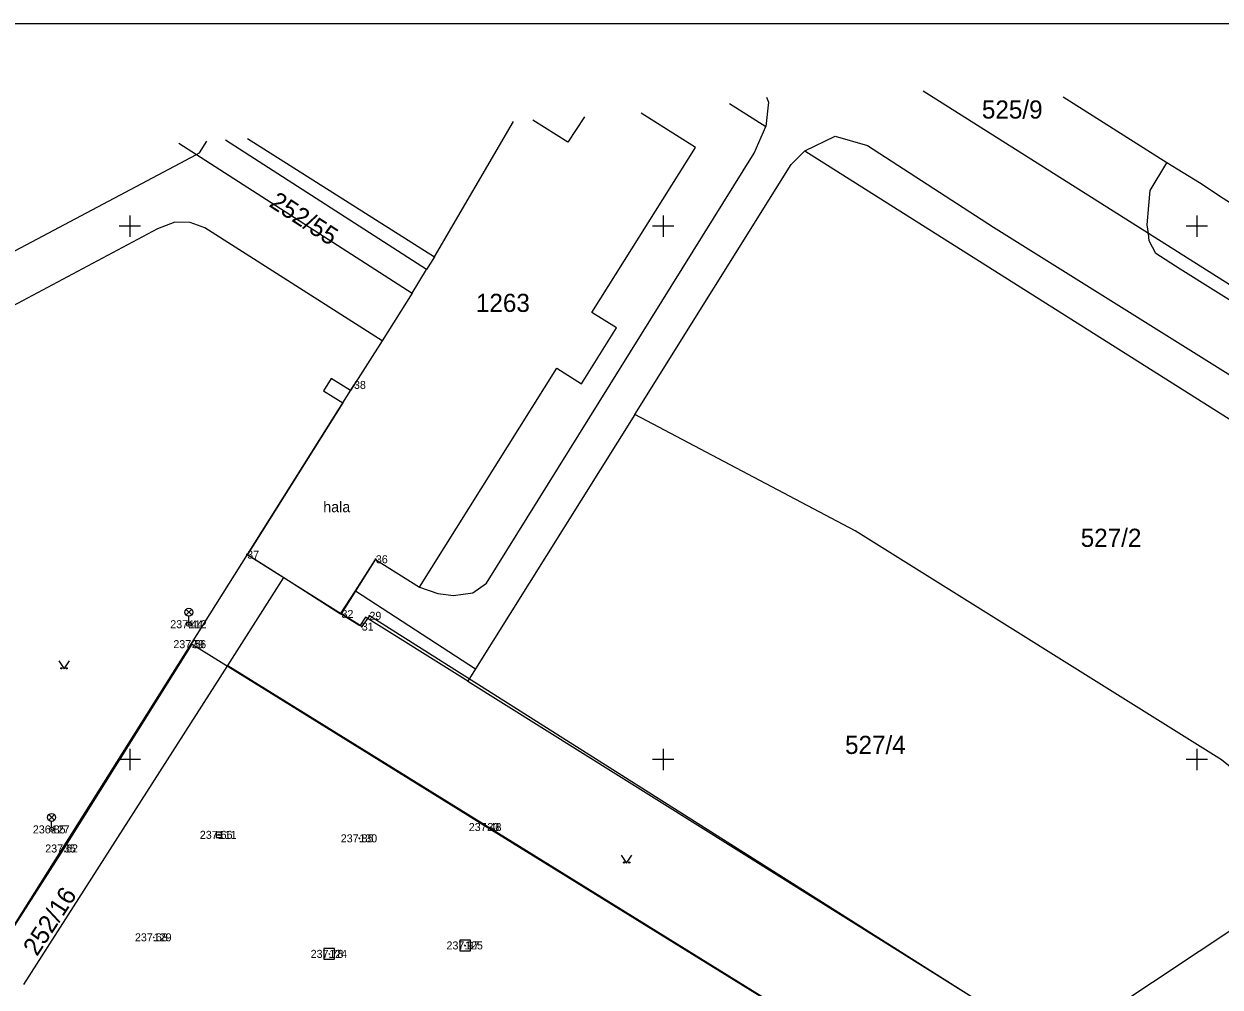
# Model space of a CAD drawing. Extents: x -645398 to -644998, y -1063322 to -1063031.
# Drawn here: x -645309.9 to -645197.8, y -1063121.3 to -1063031 of the extents above; entities that cross this region are included whole.
import ezdxf

# ---------------------------------------------------------------- set-up
doc = ezdxf.new("R2010")
doc.units = 0
for name, color, linetype in [('Bod', 7, 'Continuous'), ('Doplněk polohopisu', 7, 'Continuous'), ('Elektrický kabel', 7, 'Continuous'), ('Hranice KN pozemků', 7, 'Continuous'), ('Kanalizace', 7, 'Continuous'), ('Kultury', 7, 'Continuous'), ('Popisy budov', 7, 'Continuous'), ('Rozhraní ploch', 7, 'Continuous'), ('Rámeček', 7, 'Continuous'), ('Souřadnicové křížky', 7, 'Continuous'), ('Stavby', 7, 'Continuous'), ('Sítě podzemní nerozlišené', 7, 'Continuous'), ('Vnitřní kresba parcel', 7, 'Continuous'), ('Výška', 7, 'Continuous'), ('Čísla parcel', 7, 'Continuous'), ('Čísla stavebních parcel', 7, 'Continuous'), ('Číslo bodu', 7, 'Continuous')]:
    doc.layers.add(name, color=color, linetype=linetype)

msp = doc.modelspace()

# ---------------------------------------------------------------- linework, layer by layer
at = {"layer": 'Bod'}
for p, q in [((-645278.99, -1063064.87), (-645279.04, -1063064.82)), ((-645278.99, -1063064.87), (-645279.04, -1063064.92)), ((-645278.99, -1063064.87), (-645278.94, -1063064.82)), ((-645278.99, -1063064.87), (-645278.94, -1063064.92)), ((-645289, -1063080.79), (-645289.05, -1063080.74)), ((-645289, -1063080.79), (-645289.05, -1063080.84)), ((-645289, -1063080.79), (-645288.95, -1063080.74)), ((-645289, -1063080.79), (-645288.95, -1063080.84)), ((-645276.94, -1063081.23), (-645276.99, -1063081.18)), ((-645276.94, -1063081.23), (-645276.99, -1063081.28)), ((-645276.94, -1063081.23), (-645276.89, -1063081.18)), ((-645276.94, -1063081.23), (-645276.89, -1063081.28)), ((-645294.47, -1063087.31), (-645294.52, -1063087.26)), ((-645294.47, -1063087.31), (-645294.52, -1063087.36)), ((-645294.47, -1063087.31), (-645294.42, -1063087.26)), ((-645294.47, -1063087.31), (-645294.42, -1063087.36)), ((-645280.16, -1063086.35), (-645280.21, -1063086.3)), ((-645280.16, -1063086.35), (-645280.21, -1063086.4)), ((-645280.16, -1063086.35), (-645280.11, -1063086.3)), ((-645280.16, -1063086.35), (-645280.11, -1063086.4)), ((-645277.54, -1063086.52), (-645277.59, -1063086.47)), ((-645277.54, -1063086.52), (-645277.59, -1063086.57)), ((-645277.54, -1063086.52), (-645277.49, -1063086.47)), ((-645277.54, -1063086.52), (-645277.49, -1063086.57)), ((-645278.26, -1063087.53), (-645278.31, -1063087.48)), ((-645278.26, -1063087.53), (-645278.31, -1063087.58)), ((-645278.26, -1063087.53), (-645278.21, -1063087.48)), ((-645278.26, -1063087.53), (-645278.21, -1063087.58)), ((-645294.16, -1063089.19), (-645294.21, -1063089.14)), ((-645294.16, -1063089.19), (-645294.21, -1063089.24)), ((-645294.16, -1063089.19), (-645294.11, -1063089.14)), ((-645294.16, -1063089.19), (-645294.11, -1063089.24)), ((-645266.49, -1063106.33), (-645266.54, -1063106.28)), ((-645266.49, -1063106.33), (-645266.54, -1063106.38)), ((-645266.49, -1063106.33), (-645266.44, -1063106.28)), ((-645266.49, -1063106.33), (-645266.44, -1063106.38)), ((-645307.33, -1063106.55), (-645307.38, -1063106.5)), ((-645307.33, -1063106.55), (-645307.38, -1063106.6)), ((-645307.33, -1063106.55), (-645307.28, -1063106.5)), ((-645307.33, -1063106.55), (-645307.28, -1063106.6)), ((-645291.66, -1063107.06), (-645291.71, -1063107.01)), ((-645291.66, -1063107.06), (-645291.71, -1063107.11)), ((-645291.66, -1063107.06), (-645291.61, -1063107.01)), ((-645291.66, -1063107.06), (-645291.61, -1063107.11)), ((-645278.49, -1063107.4), (-645278.54, -1063107.35)), ((-645278.49, -1063107.4), (-645278.54, -1063107.45)), ((-645278.49, -1063107.4), (-645278.44, -1063107.35)), ((-645278.49, -1063107.4), (-645278.44, -1063107.45)), ((-645306.17, -1063108.34), (-645306.22, -1063108.29)), ((-645306.17, -1063108.34), (-645306.22, -1063108.39)), ((-645306.17, -1063108.34), (-645306.12, -1063108.29)), ((-645306.17, -1063108.34), (-645306.12, -1063108.39)), ((-645297.76, -1063116.68), (-645297.81, -1063116.63)), ((-645297.76, -1063116.68), (-645297.81, -1063116.73)), ((-645297.76, -1063116.68), (-645297.71, -1063116.63)), ((-645297.76, -1063116.68), (-645297.71, -1063116.73)), ((-645268.58, -1063117.44), (-645268.63, -1063117.39)), ((-645268.58, -1063117.44), (-645268.63, -1063117.49)), ((-645268.58, -1063117.44), (-645268.53, -1063117.39)), ((-645268.58, -1063117.44), (-645268.53, -1063117.49)), ((-645281.31, -1063118.23), (-645281.36, -1063118.18)), ((-645281.31, -1063118.23), (-645281.36, -1063118.28)), ((-645281.31, -1063118.23), (-645281.26, -1063118.18)), ((-645281.31, -1063118.23), (-645281.26, -1063118.28))]:
    msp.add_line(p, q, dxfattribs=at)
at = {"layer": 'Doplněk polohopisu'}
msp.add_lwpolyline([(-645213.53, -1063127.04), (-645277.54, -1063086.52), (-645278.26, -1063087.53), (-645280.16, -1063086.35)], dxfattribs=at)
at = {"layer": 'Elektrický kabel'}
for p, q in [((-645294.73, -1063086.45), (-645294.21, -1063085.92)), ((-645294.2, -1063086.45), (-645294.73, -1063085.92)), ((-645294.47, -1063087.11), (-645294.47, -1063086.56)), ((-645307.59, -1063105.69), (-645307.07, -1063105.16)), ((-645307.06, -1063105.69), (-645307.59, -1063105.16)), ((-645307.33, -1063106.35), (-645307.33, -1063105.8))]:
    msp.add_line(p, q, dxfattribs=at)
for centre, radius in [((-645294.47, -1063086.19), 0.375), ((-645294.47, -1063087.31), 0.2), ((-645307.33, -1063105.43), 0.375), ((-645307.33, -1063106.55), 0.2)]:
    msp.add_circle(centre, radius, dxfattribs=at)
at = {"layer": 'Hranice KN pozemků'}
for p, q in [((-645272.18, -1063054.06), (-645291.04, -1063041.91)), ((-645293.75, -1063043.27), (-645273.55, -1063056.26)), ((-645204.35, -1063046.64), (-645202.8, -1063044.04)), ((-645297.4, -1063050.24), (-645348.48, -1063077.49)), ((-645276.35, -1063060.75), (-645292.97, -1063050.16)), ((-645273.55, -1063056.26), (-645272.18, -1063054.06)), ((-645273.55, -1063056.26), (-645276.35, -1063060.75)), ((-645324.71, -1063137.53), (-645288.96, -1063080.79)), ((-645288.96, -1063080.79), (-645285.57, -1063082.93)), ((-645290.82, -1063091.17), (-645285.57, -1063082.93)), ((-645285.57, -1063082.93), (-645280.26, -1063086.33)), ((-645278.45, -1063087.48), (-645280.26, -1063086.33)), ((-645309.94, -1063121.11), (-645290.82, -1063091.17)), ((-645290.82, -1063091.17), (-645226.33, -1063131.14)), ((-645268.32, -1063092.65), (-645213.42, -1063127.02)), ((-645213.42, -1063127.02), (-645186.47, -1063109.12))]:
    msp.add_line(p, q, dxfattribs=at)
for points in [[(-645204.52, -1063050.69), (-645225.65, -1063037.34)], [(-645202.8, -1063044.04), (-645212.52, -1063037.89)], [(-645280.26, -1063086.33), (-645278.86, -1063084.17), (-645276.97, -1063081.25), (-645272.86, -1063083.83), (-645259.97, -1063063.31), (-645257.66, -1063064.76), (-645254.37, -1063059.51), (-645256.68, -1063058.07), (-645246.97, -1063042.62), (-645252.08, -1063039.39)], [(-645257.39, -1063039.73), (-645258.95, -1063042.11), (-645262.24, -1063040.05)], [(-645295.42, -1063042.19), (-645293.75, -1063043.27)], [(-645293.75, -1063043.27), (-645293.47, -1063043.12), (-645292.79, -1063042.02)], [(-645288.97, -1063041.78), (-645271.43, -1063052.86), (-645272.18, -1063054.06)], [(-645236.73, -1063042.91), (-645233.9, -1063041.56), (-645230.85, -1063042.43), (-645219.03, -1063050.07), (-645152.72, -1063091.57), (-645140.39, -1063099.29), (-645051.35, -1063155.61)], [(-645343.9, -1063052.83), (-645337.14, -1063056.96), (-645328.72, -1063059.37), (-645321.06, -1063057.75), (-645293.75, -1063043.27)], [(-645252.67, -1063067.66), (-645238, -1063044.21), (-645236.73, -1063042.91)], [(-645236.73, -1063042.91), (-645154.72, -1063094.74), (-645140.39, -1063103.8), (-645055.15, -1063157.46)], [(-645168.41, -1063048.3), (-645168.62, -1063048.16), (-645173.43, -1063055.26), (-645176.87, -1063060.58), (-645197.51, -1063047.38), (-645199.73, -1063045.93), (-645202.8, -1063044.04)], [(-645204.52, -1063050.69), (-645204.63, -1063049.86), (-645204.48, -1063048.05), (-645204.35, -1063046.64)], [(-645292.97, -1063050.16), (-645294.36, -1063049.64), (-645295.77, -1063049.62), (-645297.4, -1063050.24)], [(-645149.78, -1063063.57), (-645159.6, -1063079.08), (-645204.52, -1063050.69)], [(-645203.84, -1063052.54), (-645204.44, -1063051.35), (-645204.52, -1063050.69)], [(-645148.3, -1063087.54), (-645149.64, -1063086.69), (-645177.4, -1063069.18), (-645179.16, -1063068.05), (-645201.56, -1063054.02), (-645203.84, -1063052.54)], [(-645276.35, -1063060.75), (-645279.31, -1063065.41), (-645281.13, -1063064.28), (-645281.86, -1063065.42), (-645280.03, -1063066.56), (-645288.96, -1063080.79)], [(-645252.67, -1063067.66), (-645267.59, -1063091.49), (-645268.32, -1063092.65)], [(-645186.47, -1063109.12), (-645197.66, -1063100.03), (-645232, -1063078.56), (-645252.67, -1063067.66)], [(-645268.32, -1063092.65), (-645277.91, -1063086.64), (-645278.45, -1063087.48)]]:
    msp.add_lwpolyline(points, dxfattribs=at)
at = {"layer": 'Kanalizace'}
msp.add_line((-645291.91, -1063107.06), (-645291.41, -1063107.06), dxfattribs=at)
msp.add_lwpolyline([(-645291.91, -1063107.31), (-645291.41, -1063107.31), (-645291.41, -1063106.81), (-645291.91, -1063106.81)], close=True, dxfattribs=at)
at = {"layer": 'Kultury'}
for points in [[(-645306.67, -1063090.75), (-645306.17, -1063091.5), (-645305.67, -1063090.75)], [(-645253.93, -1063108.96), (-645253.43, -1063109.71), (-645252.93, -1063108.96)]]:
    msp.add_lwpolyline(points, dxfattribs=at)
for centre in [(-645306.42, -1063091.45), (-645305.92, -1063091.45), (-645253.68, -1063109.66), (-645253.18, -1063109.66)]:
    msp.add_circle(centre, 0.05, dxfattribs=at)
at = {"layer": 'Rozhraní ploch'}
msp.add_lwpolyline([(-645324.89, -1063137.57), (-645306.17, -1063108.34), (-645294.16, -1063089.19), (-645266.49, -1063106.33), (-645238.82, -1063123.47), (-645226.63, -1063131.07), (-645233.92, -1063142.75), (-645244.93, -1063160.38), (-645255.94, -1063178.02)], dxfattribs=at)
at = {"layer": 'Rámeček'}
msp.add_line((-644998.25, -1063031.02), (-645398.25, -1063031.02), dxfattribs=at)
at = {"layer": 'Souřadnicové křížky'}
for p, q in [((-645300, -1063049), (-645300, -1063051)), ((-645250, -1063049), (-645250, -1063051)), ((-645200, -1063049), (-645200, -1063051)), ((-645299, -1063050), (-645301, -1063050)), ((-645249, -1063050), (-645251, -1063050)), ((-645199, -1063050), (-645201, -1063050)), ((-645300, -1063099), (-645300, -1063101)), ((-645250, -1063099), (-645250, -1063101)), ((-645200, -1063099), (-645200, -1063101)), ((-645299, -1063100), (-645301, -1063100)), ((-645249, -1063100), (-645251, -1063100)), ((-645199, -1063100), (-645201, -1063100))]:
    msp.add_line(p, q, dxfattribs=at)
at = {"layer": 'Stavby'}
for p, q in [((-645278.99, -1063064.87), (-645289, -1063080.79)), ((-645289, -1063080.79), (-645280.16, -1063086.35)), ((-645280.16, -1063086.35), (-645276.94, -1063081.23))]:
    msp.add_line(p, q, dxfattribs=at)
at = {"layer": 'Sítě podzemní nerozlišené'}
for p, q in [((-645268.08, -1063116.94), (-645269.08, -1063116.94)), ((-645269.08, -1063116.94), (-645269.08, -1063117.94)), ((-645268.08, -1063117.94), (-645268.08, -1063116.94)), ((-645280.81, -1063117.73), (-645281.81, -1063117.73)), ((-645281.81, -1063117.73), (-645281.81, -1063118.73)), ((-645280.81, -1063118.73), (-645280.81, -1063117.73)), ((-645269.08, -1063117.94), (-645268.08, -1063117.94)), ((-645281.81, -1063118.73), (-645280.81, -1063118.73))]:
    msp.add_line(p, q, dxfattribs=at)
at = {"layer": 'Vnitřní kresba parcel'}
for p, q in [((-645240.33, -1063037.88), (-645240.13, -1063038.36)), ((-645243.8, -1063038.48), (-645240.37, -1063040.65)), ((-645240.13, -1063038.36), (-645240.37, -1063040.65)), ((-645271.43, -1063052.86), (-645264.04, -1063040.16)), ((-645241.47, -1063043.14), (-645240.37, -1063040.65)), ((-645266.56, -1063083.48), (-645241.47, -1063043.14)), ((-645272.86, -1063083.83), (-645271.12, -1063084.43)), ((-645267.84, -1063084.37), (-645266.56, -1063083.48)), ((-645278.86, -1063084.17), (-645267.59, -1063091.49)), ((-645271.12, -1063084.43), (-645269.65, -1063084.61)), ((-645269.65, -1063084.61), (-645267.84, -1063084.37))]:
    msp.add_line(p, q, dxfattribs=at)

# ---------------------------------------------------------------- texts
at = {"layer": 'Popisy budov'}
msp.add_text('hala', height=1, dxfattribs=at).set_placement((-645281.87, -1063076.81))
at = {"layer": 'Výška'}
for s, p in [('237.44', (-645296.21, -1063087.69)), ('237.56', (-645295.92, -1063089.56)), ('236.85', (-645309.09, -1063106.93)), ('237.48', (-645268.23, -1063106.71)), ('237.66', (-645293.44, -1063107.44)), ('237.85', (-645280.23, -1063107.77)), ('237.62', (-645307.93, -1063108.72)), ('237.68', (-645299.52, -1063117.05)), ('237.97', (-645270.32, -1063117.81)), ('237.78', (-645283.05, -1063118.6))]:
    msp.add_text(s, height=0.75, dxfattribs=at).set_placement(p)
at = {"layer": 'Čísla parcel'}
for s, p in [('525/9', (-645220.13, -1063039.9)), ('527/2', (-645210.87, -1063080.06)), ('527/4', (-645232.96, -1063099.48))]:
    msp.add_text(s, height=1.7, dxfattribs=at).set_placement(p)
for s, rotation, p in [('252/55', 327, (-645287.04, -1063048.08)), ('252/16', 57, (-645308.7, -1063118.52))]:
    msp.add_text(s, height=1.7, rotation=rotation, dxfattribs=at).set_placement(p)
at = {"layer": 'Čísla stavebních parcel'}
msp.add_text('1263', height=1.7, dxfattribs=at).set_placement((-645267.56, -1063058.03))
at = {"layer": 'Číslo bodu'}
for s, p in [('38', (-645278.99, -1063065.25)), ('37', (-645289, -1063081.17)), ('36', (-645276.94, -1063081.6)), ('32', (-645280.16, -1063086.73)), ('29', (-645277.54, -1063086.9)), ('112', (-645294.47, -1063087.69)), ('31', (-645278.26, -1063087.91)), ('39', (-645294.16, -1063089.56)), ('127', (-645307.33, -1063106.93)), ('33', (-645266.49, -1063106.71)), ('111', (-645291.66, -1063107.44)), ('130', (-645278.49, -1063107.77)), ('35', (-645306.17, -1063108.72)), ('129', (-645297.76, -1063117.05)), ('125', (-645268.58, -1063117.81)), ('124', (-645281.31, -1063118.6))]:
    msp.add_text(s, height=0.75, dxfattribs=at).set_placement(p)

doc.saveas('drawing.dxf')
